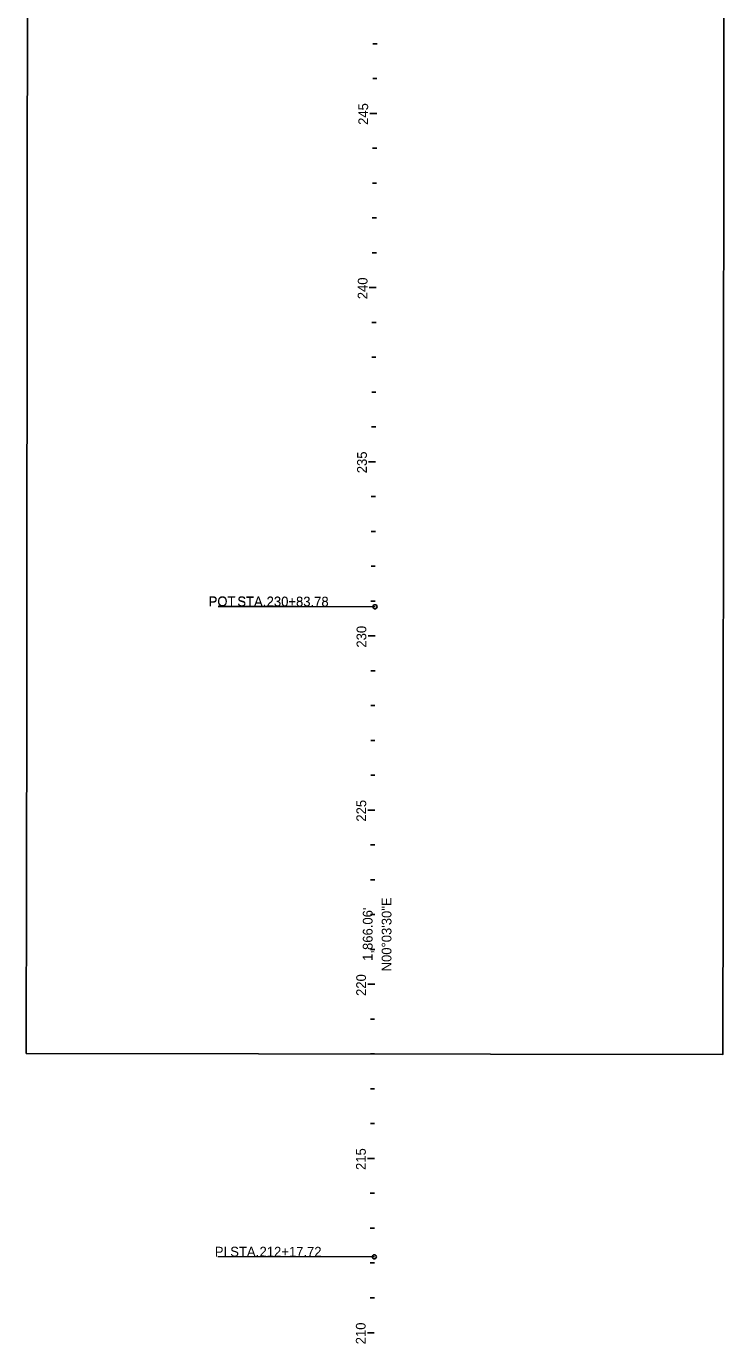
# Model space of a CAD drawing. Extents: x 1807668 to 1809726, y 297763 to 325145.
# Drawn here: x 1807668 to 1809673, y 301538 to 305319 of the extents above; entities that cross this region are included whole.
import ezdxf

# ---------------------------------------------------------------- set-up
doc = ezdxf.new("R2010")
doc.units = 0
for name, color, linetype in [('GE_P_Alignment_500_Bearings', 7, 'Continuous'), ('GE_P_Alignment_500_Cardinal_Points', 7, 'Continuous'), ('GE_P_Alignment_500_Distances', 7, 'Continuous'), ('GE_P_Alignment_500_Stations', 7, 'Continuous'), ('SH_Named_Boundary', 7, 'Continuous')]:
    doc.layers.add(name, color=color, linetype=linetype)

msp = doc.modelspace()

# ---------------------------------------------------------------- linework, layer by layer
at = {"layer": 'GE_P_Alignment_500_Cardinal_Points'}
for p, q in [((1808669.4, 303653), (1808219.4, 303654.6)), ((1808669.4, 303653), (1808219.4, 303653.5)), ((1808667.5, 301786.9), (1808217.5, 301787.4))]:
    msp.add_line(p, q, dxfattribs=at)
for centre in [(1808669.4, 303653), (1808669.4, 303653), (1808667.5, 301786.9)]:
    msp.add_circle(centre, 6, dxfattribs=at)
at = {"layer": 'GE_P_Alignment_500_Stations'}
for p, q in [((1808675.3, 305269.2), (1808663.3, 305269.3)), ((1808674.9, 305169.2), (1808662.9, 305169.3)), ((1808674.5, 305069.2), (1808654.5, 305069.3)), ((1808674.2, 304969.2), (1808662.2, 304969.3)), ((1808673.8, 304869.2), (1808661.8, 304869.3)), ((1808673.5, 304769.2), (1808661.5, 304769.3)), ((1808673.1, 304669.2), (1808661.1, 304669.3)), ((1808672.7, 304569.2), (1808652.7, 304569.3)), ((1808672.4, 304469.2), (1808660.4, 304469.3)), ((1808672, 304369.2), (1808660, 304369.3)), ((1808671.7, 304269.2), (1808659.7, 304269.3)), ((1808671.3, 304169.2), (1808659.3, 304169.3)), ((1808670.9, 304069.2), (1808650.9, 304069.3)), ((1808670.6, 303969.2), (1808658.6, 303969.3)), ((1808670.2, 303869.2), (1808658.2, 303869.3)), ((1808669.9, 303769.2), (1808657.9, 303769.3)), ((1808669.5, 303669.2), (1808657.5, 303669.3)), ((1808669.4, 303569.2), (1808649.4, 303569.2)), ((1808669.3, 303469.2), (1808657.3, 303469.2)), ((1808669.2, 303369.2), (1808657.2, 303369.2)), ((1808669, 303269.2), (1808657, 303269.2)), ((1808668.9, 303169.2), (1808656.9, 303169.2)), ((1808668.8, 303069.2), (1808648.8, 303069.2)), ((1808668.7, 302969.2), (1808656.7, 302969.2)), ((1808668.6, 302869.2), (1808656.6, 302869.2)), ((1808668.5, 302769.2), (1808656.5, 302769.2)), ((1808668.4, 302669.2), (1808656.4, 302669.2)), ((1808668.3, 302569.2), (1808648.3, 302569.2)), ((1808668.2, 302469.2), (1808656.2, 302469.2)), ((1808668.1, 302369.2), (1808656.1, 302369.2)), ((1808668, 302269.2), (1808656, 302269.2)), ((1808667.9, 302169.2), (1808655.9, 302169.2)), ((1808667.8, 302069.2), (1808647.8, 302069.2)), ((1808667.7, 301969.2), (1808655.7, 301969.2)), ((1808667.6, 301869.2), (1808655.6, 301869.2)), ((1808667.5, 301769.2), (1808655.5, 301769.2)), ((1808667.4, 301669.2), (1808655.4, 301669.2)), ((1808667.3, 301569.2), (1808647.3, 301569.2))]:
    msp.add_line(p, q, dxfattribs=at)
at = {"layer": 'SH_Named_Boundary'}
msp.add_lwpolyline([(1807668.1, 302370.2), (1809668.1, 302368.2), (1809668.6, 302868.2), (1809669.2, 303368.2), (1809669.7, 303868.2), (1809670.2, 304368.2), (1809670.7, 304868.2), (1809671.2, 305368.2), (1809671.7, 305868.2), (1809672.2, 306368.2), (1809672.7, 306868.2), (1809673.2, 307368.2), (1807673.2, 307370.3), (1807672.7, 306870.3), (1807672.2, 306370.3), (1807671.7, 305870.3), (1807671.2, 305370.3), (1807670.7, 304870.2), (1807670.2, 304370.2), (1807669.7, 303870.2), (1807669.2, 303370.2), (1807668.6, 302870.2)], close=True, dxfattribs=at)

# ---------------------------------------------------------------- texts
at = {"layer": 'GE_P_Alignment_500_Bearings'}
msp.add_text('N00°03\'30"E', height=28, rotation=89.9418, dxfattribs=at).set_placement((1808716.4, 302606.3))
at = {"layer": 'GE_P_Alignment_500_Cardinal_Points'}
for s, rotation, p in [('POT', 359.7937, (1808191.6, 303655.1)), ('POT', 359.9418, (1808191.6, 303653.9)), (' STA. ', 359.7937, (1808263.6, 303654.9)), (' STA. ', 359.9418, (1808263.6, 303653.8)), ('230+83.78', 359.7937, (1808358.1, 303654.5)), ('230+83.78', 359.9418, (1808358.1, 303653.7)), ('PI', 359.9418, (1808209.3, 301787.8)), (' STA. ', 359.9418, (1808243.2, 301787.8)), ('212+17.72', 359.9418, (1808337.7, 301787.7))]:
    msp.add_text(s, height=28, rotation=rotation, dxfattribs=at).set_placement(p)
at = {"layer": 'GE_P_Alignment_500_Distances'}
msp.add_text("1,866.06'", height=28, rotation=89.9418, dxfattribs=at).set_placement((1808662.2, 302636.5))
at = {"layer": 'GE_P_Alignment_500_Stations'}
for s, rotation, p in [('245', 89.7937, (1808649.4, 305036.3)), ('240', 89.7937, (1808647.6, 304535.8)), ('235', 89.7937, (1808645.8, 304036.3)), ('230', 89.9418, (1808644.3, 303535.8)), ('225', 89.9418, (1808643.8, 303036.2)), ('220', 89.9418, (1808643.3, 302535.8)), ('215', 89.9418, (1808642.8, 302036.2)), ('210', 89.9418, (1808642.3, 301535.8))]:
    msp.add_text(s, height=28, rotation=rotation, dxfattribs=at).set_placement(p)

doc.saveas('drawing.dxf')
